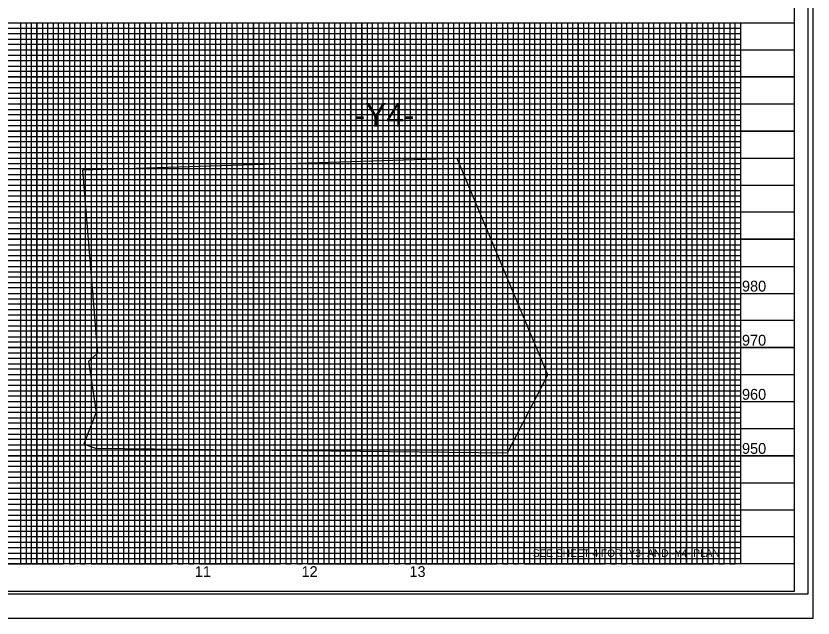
# Model space of a CAD drawing. Extents: x 1624665 to 1626605, y 896887 to 897987.
# Drawn here: x 1625613 to 1626349, y 896887 to 897444 of the extents above; entities that cross this region are included whole.
import ezdxf

# ---------------------------------------------------------------- set-up
doc = ezdxf.new("R2010")
doc.units = 0
for name, color, linetype in [('Prop DSN Text', 7, 'Continuous'), ('Prop PHM Black Shape', 7, 'Continuous'), ('Scratch_Level_1', 7, 'Continuous'), ('Sheet Cutting Line CELL', 7, 'Continuous'), ('Sheet DOT Grid CELL', 7, 'Continuous'), ('Sheet Layout Profile Border Port 2', 7, 'Continuous'), ('Sheet Plot Border Inside CELL', 7, 'Continuous'), ('Sheet Plot Border Outside CELL', 7, 'Continuous'), ('Sheet Profile CELL', 7, 'Continuous'), ('Sheet Profile Grid Major CELL', 7, 'Continuous'), ('Sheet Profile Grid Middle CELL', 7, 'Continuous'), ('Sheet Profile Grid Minor CELL', 7, 'Continuous')]:
    doc.layers.add(name, color=color, linetype=linetype)

msp = doc.modelspace()

# ---------------------------------------------------------------- linework, layer by layer
at = {"layer": 'Prop DSN Text'}
msp.add_lwpolyline([(1625922.4, 897367.44), (1625992.4, 897367.44), (1625992.4, 897337.44), (1625922.4, 897337.44)], close=True, dxfattribs=at)
at = {"layer": 'Prop PHM Black Shape'}
for points in [[(1625922.4, 897367.44), (1625992.4, 897367.44), (1625992.4, 897337.44), (1625922.4, 897337.44)], [(1626082.4, 896957.44), (1626282.4, 896957.44), (1626282.4, 896937.44), (1626082.4, 896937.44)]]:
    msp.add_lwpolyline(points, close=True, dxfattribs=at)
at = {"layer": 'Scratch_Level_1'}
msp.add_lwpolyline([(1625687.54, 897143.34), (1625688.21, 897132.26), (1625680.13, 897124.65), (1625687.11, 897077.78), (1625675.77, 897048.03), (1625686.55, 897044.37), (1626067.2, 897040.06), (1626104.5, 897112.25), (1626020.67, 897312.19), (1625674.55, 897301.26)], close=True, dxfattribs=at)
at = {"layer": 'Sheet Cutting Line CELL'}
msp.add_line((1624665.4, 896887.44), (1626349.4, 896887.44), dxfattribs=at)
at = {"layer": 'Sheet DOT Grid CELL'}
for p, q in [((1624832.4, 897437.44), (1626332.29, 897437.44)), ((1625632.4, 897437.44), (1625632.4, 896937.44)), ((1625682.4, 897437.44), (1625682.4, 896937.44)), ((1625732.4, 897437.44), (1625732.4, 896937.44)), ((1625782.4, 897437.44), (1625782.4, 896937.44)), ((1625832.4, 897437.44), (1625832.4, 896937.44)), ((1625882.4, 897437.44), (1625882.4, 896937.44)), ((1625932.4, 897437.44), (1625932.4, 896937.44)), ((1625982.4, 897437.44), (1625982.4, 896937.44)), ((1626032.4, 897437.44), (1626032.4, 896937.44)), ((1626082.4, 897437.44), (1626082.4, 896937.44)), ((1626132.4, 897437.44), (1626132.4, 896937.44)), ((1626182.4, 897437.44), (1626182.4, 896937.44)), ((1626232.4, 897437.44), (1626232.4, 896937.44)), ((1626282.4, 897437.44), (1626282.4, 896937.44)), ((1624832.4, 897387.44), (1626332.29, 897387.44)), ((1624832.4, 897337.44), (1626332.29, 897337.44)), ((1624832.4, 897287.44), (1626332.29, 897287.44)), ((1624832.4, 897237.44), (1626332.29, 897237.44)), ((1624832.4, 897187.44), (1626332.29, 897187.44)), ((1624832.4, 897137.44), (1626332.29, 897137.44)), ((1624832.4, 897087.44), (1626332.29, 897087.44)), ((1624832.4, 897037.44), (1626332.29, 897037.44)), ((1624832.4, 896987.44), (1626332.29, 896987.44))]:
    msp.add_line(p, q, dxfattribs=at)
at = {"layer": 'Sheet Layout Profile Border Port 2'}
msp.add_lwpolyline([(1624882.4, 897437.44), (1626282.4, 897437.44), (1626282.4, 896937.44), (1624882.4, 896937.44)], close=True, dxfattribs=at)
at = {"layer": 'Sheet Plot Border Inside CELL'}
msp.add_lwpolyline([(1624678.4, 896909.89), (1626344.9, 896909.89), (1626344.9, 897964.99), (1624678.4, 897964.99)], close=True, dxfattribs=at)
at = {"layer": 'Sheet Plot Border Outside CELL'}
msp.add_lwpolyline([(1624665.4, 896887.44), (1626349.4, 896887.44), (1626349.4, 897987.44), (1624665.4, 897987.44)], close=True, dxfattribs=at)
at = {"layer": 'Sheet Profile CELL'}
for p, q in [((1624832.4, 897437.44), (1626332.4, 897437.44)), ((1626332.4, 896937.44), (1624832.4, 896937.44)), ((1624832.4, 896912.44), (1626332.4, 896912.44))]:
    msp.add_line(p, q, dxfattribs=at)
msp.add_lwpolyline([(1626332.4, 897962.44), (1624832.4, 897962.44), (1624832.4, 896912.44), (1626332.4, 896912.44)], close=True, dxfattribs=at)
at = {"layer": 'Sheet Profile Grid Major CELL'}
for p, q in [((1625632.4, 897437.44), (1625682.4, 897437.44)), ((1625732.4, 897437.44), (1625782.4, 897437.44)), ((1625832.4, 897437.44), (1625882.4, 897437.44)), ((1625932.4, 897437.44), (1625982.4, 897437.44)), ((1626032.4, 897437.44), (1626082.4, 897437.44)), ((1626132.4, 897437.44), (1626182.4, 897437.44)), ((1626232.4, 897437.44), (1626282.4, 897437.44)), ((1626232.4, 896937.44), (1626232.4, 896937.44))]:
    msp.add_line(p, q, dxfattribs=at)
for points in [[(1625582.4, 896937.44), (1625632.4, 896937.44), (1625632.4, 897437.44), (1625682.4, 897437.44), (1625682.4, 896937.44), (1625732.4, 896937.44), (1625732.4, 897437.44), (1625782.4, 897437.44), (1625782.4, 896937.44), (1625832.4, 896937.44), (1625832.4, 897437.44), (1625882.4, 897437.44), (1625882.4, 896937.44), (1625932.4, 896937.44), (1625932.4, 897437.44), (1625982.4, 897437.44), (1625982.4, 896937.44), (1626032.4, 896937.44), (1626032.4, 897437.44), (1626082.4, 897437.44), (1626082.4, 896937.44), (1626132.4, 896937.44), (1626132.4, 897437.44), (1626182.4, 897437.44), (1626182.4, 896937.44), (1626232.4, 896937.44), (1626232.4, 896937.44), (1626232.4, 897437.44), (1626282.4, 897437.44), (1626282.4, 896937.44)], [(1626332.4, 897387.44), (1624832.4, 897387.44)], [(1626332.4, 897337.44), (1624832.4, 897337.44), (1624832.4, 897287.44), (1626332.4, 897287.44)], [(1626332.4, 897237.44), (1624832.4, 897237.44), (1624832.4, 897187.44), (1626332.4, 897187.44)], [(1626332.4, 897137.44), (1624832.4, 897137.44), (1624832.4, 897087.44), (1626332.4, 897087.44)], [(1626332.4, 897037.44), (1624832.4, 897037.44), (1624832.4, 897037.44), (1624832.4, 896987.44), (1626332.4, 896987.44)], [(1626332.4, 896937.44), (1624832.4, 896937.44)]]:
    msp.add_lwpolyline(points, dxfattribs=at)
at = {"layer": 'Sheet Profile Grid Middle CELL'}
for points in [[(1625607.4, 896937.44), (1625657.4, 896937.44), (1625657.4, 897437.44), (1625707.4, 897437.44), (1625707.4, 896937.44), (1625757.4, 896937.44), (1625757.4, 897437.44), (1625807.4, 897437.44), (1625807.4, 896937.44), (1625857.4, 896937.44), (1625857.4, 897437.44), (1625907.4, 897437.44), (1625907.4, 896937.44), (1625957.4, 896937.44), (1625957.4, 897437.44), (1626007.4, 897437.44), (1626007.4, 896937.44), (1626057.4, 896937.44), (1626057.4, 897437.44), (1626107.4, 897437.44), (1626107.4, 896937.44), (1626157.4, 896937.44), (1626157.4, 897437.44), (1626207.4, 897437.44), (1626207.4, 896937.44), (1626257.4, 896937.44), (1626257.4, 897437.44)], [(1624832.4, 897412.44), (1626332.4, 897412.44)], [(1626332.4, 897362.44), (1624832.4, 897362.44), (1624832.4, 897312.44), (1626332.4, 897312.44)], [(1626332.4, 897262.44), (1624832.4, 897262.44), (1624832.4, 897212.44), (1626332.4, 897212.44)], [(1626332.4, 897162.44), (1624832.4, 897162.44), (1624832.4, 897112.44), (1626332.4, 897112.44)], [(1626332.4, 897062.44), (1624832.4, 897062.44), (1624832.4, 897012.44), (1626332.4, 897012.44)], [(1626332.4, 896962.44), (1624832.4, 896962.44)]]:
    msp.add_lwpolyline(points, dxfattribs=at)
at = {"layer": 'Sheet Profile Grid Minor CELL'}
for p, q in [((1624882.4, 897432.44), (1626282.4, 897432.44)), ((1626282.4, 897427.44), (1624882.4, 897427.44)), ((1624882.4, 897422.44), (1626282.4, 897422.44)), ((1626282.4, 897417.44), (1624882.4, 897417.44)), ((1624882.4, 897407.44), (1626282.4, 897407.44)), ((1626282.4, 897402.44), (1624882.4, 897402.44)), ((1624882.4, 897397.44), (1626282.4, 897397.44)), ((1626282.4, 897392.44), (1624882.4, 897392.44)), ((1624882.4, 897382.44), (1626282.4, 897382.44)), ((1626282.4, 897377.44), (1624882.4, 897377.44)), ((1624882.4, 897372.44), (1626282.4, 897372.44)), ((1626282.4, 897367.44), (1624882.4, 897367.44)), ((1624882.4, 897357.44), (1626282.4, 897357.44)), ((1626282.4, 897352.44), (1624882.4, 897352.44)), ((1624882.4, 897347.44), (1626282.4, 897347.44)), ((1626282.4, 897342.44), (1624882.4, 897342.44)), ((1624882.4, 897332.44), (1626282.4, 897332.44)), ((1626282.4, 897327.44), (1624882.4, 897327.44)), ((1624882.4, 897322.44), (1626282.4, 897322.44)), ((1626282.4, 897317.44), (1624882.4, 897317.44)), ((1624882.4, 897307.44), (1626282.4, 897307.44)), ((1626282.4, 897302.44), (1624882.4, 897302.44)), ((1624882.4, 897297.44), (1626282.4, 897297.44)), ((1626282.4, 897292.44), (1624882.4, 897292.44)), ((1624882.4, 897282.44), (1626282.4, 897282.44)), ((1626282.4, 897277.44), (1624882.4, 897277.44)), ((1624882.4, 897272.44), (1626282.4, 897272.44)), ((1626282.4, 897267.44), (1624882.4, 897267.44)), ((1624882.4, 897257.44), (1626282.4, 897257.44)), ((1626282.4, 897252.44), (1624882.4, 897252.44)), ((1624882.4, 897247.44), (1626282.4, 897247.44)), ((1626282.4, 897242.44), (1624882.4, 897242.59)), ((1624882.4, 897232.44), (1626282.4, 897232.44)), ((1626282.4, 897227.44), (1624882.4, 897227.44)), ((1624882.4, 897222.44), (1626282.4, 897222.44)), ((1626282.4, 897217.44), (1624882.4, 897217.44)), ((1624882.4, 897207.44), (1626282.4, 897207.44)), ((1626282.4, 897202.44), (1624882.4, 897202.44)), ((1624882.4, 897197.44), (1626282.4, 897197.44)), ((1626282.4, 897192.44), (1624882.4, 897192.44)), ((1624882.4, 897182.44), (1626282.4, 897182.44)), ((1626282.4, 897177.44), (1624882.4, 897177.44)), ((1624882.4, 897172.44), (1626282.4, 897172.44)), ((1626282.4, 897167.44), (1624882.4, 897167.44)), ((1624882.4, 897157.44), (1626282.4, 897157.44)), ((1626282.4, 897152.44), (1624882.4, 897152.44)), ((1624882.4, 897147.44), (1626282.4, 897147.44)), ((1626282.4, 897142.44), (1624882.4, 897142.44)), ((1624882.4, 897132.44), (1626282.4, 897132.44)), ((1626282.4, 897127.44), (1624882.4, 897127.44)), ((1624882.4, 897122.44), (1626282.4, 897122.44)), ((1626282.4, 897117.44), (1624882.4, 897117.44)), ((1624882.4, 897107.44), (1626282.4, 897107.44)), ((1626282.4, 897102.44), (1624882.4, 897102.44)), ((1624882.4, 897097.44), (1626282.4, 897097.44)), ((1626282.4, 897092.44), (1624882.4, 897092.44)), ((1624882.4, 897082.44), (1626282.4, 897082.44)), ((1626282.4, 897077.44), (1624882.4, 897077.44)), ((1624882.4, 897072.44), (1626282.4, 897072.44)), ((1626282.4, 897067.44), (1624882.4, 897067.44)), ((1624882.4, 897057.44), (1626282.4, 897057.44)), ((1626282.4, 897052.44), (1624882.4, 897052.44)), ((1624882.4, 897047.44), (1626282.4, 897047.44)), ((1626282.4, 897042.44), (1624882.4, 897042.44)), ((1624882.4, 897032.44), (1626282.4, 897032.44)), ((1626282.4, 897027.44), (1624882.4, 897027.44)), ((1624882.4, 897022.44), (1626282.4, 897022.44)), ((1626282.4, 897017.44), (1624882.4, 897017.44)), ((1624882.4, 897007.44), (1626282.4, 897007.44)), ((1626282.4, 897002.44), (1624882.4, 897002.44)), ((1624882.4, 896997.44), (1626282.4, 896997.44)), ((1626282.4, 896992.44), (1624882.4, 896992.44)), ((1624882.4, 896982.44), (1626282.4, 896982.44)), ((1626282.4, 896977.44), (1624882.4, 896977.44)), ((1624882.4, 896972.44), (1626282.4, 896972.44)), ((1626282.4, 896967.44), (1624882.4, 896967.44)), ((1624882.4, 896957.44), (1626282.4, 896957.44)), ((1626282.4, 896952.44), (1624882.4, 896952.44)), ((1624882.4, 896947.44), (1626282.4, 896947.44)), ((1624882.4, 896942.44), (1626282.4, 896942.44)), ((1626282.4, 896942.44), (1626282.4, 896942.44))]:
    msp.add_line(p, q, dxfattribs=at)
for points in [[(1625612.4, 896937.44), (1625617.4, 896937.44), (1625617.4, 897437.44), (1625622.4, 897437.44), (1625622.4, 896937.44), (1625627.4, 896937.44), (1625627.4, 897437.44), (1625637.4, 897437.44), (1625637.4, 896937.44), (1625642.4, 896937.44), (1625642.4, 897437.44), (1625647.4, 897437.44), (1625647.4, 896937.44), (1625652.4, 896937.44), (1625652.4, 897437.44), (1625662.4, 897437.44), (1625662.4, 896937.44), (1625667.4, 896937.44), (1625667.4, 897437.44), (1625672.4, 897437.44), (1625672.4, 896937.44), (1625677.4, 896937.44), (1625677.4, 897437.44), (1625687.4, 897437.44), (1625687.4, 896937.44), (1625692.1, 896937.99), (1625692.4, 896937.44), (1625692.4, 897437.44), (1625697.4, 897437.44), (1625697.4, 896937.44), (1625702.4, 896937.44), (1625702.4, 897437.44), (1625712.4, 897437.44), (1625712.4, 896937.44), (1625717.4, 896937.44)], [(1625717.4, 896937.44), (1625717.4, 897437.44), (1625722.4, 897437.44), (1625722.4, 896937.44), (1625727.4, 896937.44), (1625727.4, 897437.44), (1625737.4, 897437.44), (1625737.4, 896937.44), (1625742.4, 896937.44), (1625742.4, 897437.44), (1625747.4, 897437.44), (1625747.4, 896937.44), (1625752.4, 896937.44), (1625752.4, 897437.44), (1625762.4, 897437.44), (1625762.4, 896937.44), (1625767.4, 896937.44), (1625767.4, 897437.44), (1625772.4, 897437.44), (1625772.4, 896937.44), (1625777.4, 896937.44), (1625777.4, 897437.44), (1625787.4, 897437.44), (1625787.4, 896937.44), (1625792.4, 896937.44), (1625792.4, 897437.44), (1625797.4, 897437.44), (1625797.4, 896937.44), (1625802.4, 896937.44), (1625802.4, 897437.44), (1625812.4, 897437.44), (1625812.4, 896937.44), (1625817.4, 896937.44), (1625817.4, 897437.44), (1625822.4, 897437.44), (1625822.4, 896937.44), (1625827.4, 896937.44), (1625827.4, 897437.44), (1625837.4, 897437.44), (1625837.4, 896937.44), (1625842.4, 896937.44), (1625842.4, 897437.44), (1625847.4, 897437.44), (1625847.4, 896937.44), (1625852.4, 896937.44), (1625852.4, 897437.44), (1625862.4, 897437.44), (1625862.4, 896937.44), (1625867.4, 896937.44), (1625867.4, 897437.44), (1625872.4, 897437.44), (1625872.4, 896937.44), (1625877.4, 896937.44), (1625877.4, 897437.44), (1625887.4, 897437.44), (1625887.4, 896937.44), (1625892.4, 896937.44), (1625892.4, 897437.44), (1625897.4, 897437.44), (1625897.4, 896937.44), (1625902.4, 896937.44), (1625902.4, 897437.44), (1625912.4, 897437.44), (1625912.4, 896937.44), (1625917.4, 896937.44), (1625917.4, 897437.44), (1625922.4, 897437.44), (1625922.4, 896937.44), (1625927.4, 896937.44), (1625927.4, 897437.44), (1625937.4, 897437.44), (1625937.4, 896937.44), (1625942.4, 896937.44), (1625942.4, 897437.44), (1625947.4, 897437.44), (1625947.4, 896937.44), (1625952.4, 896937.44), (1625952.4, 897437.44), (1625962.4, 897437.44), (1625962.4, 896937.44), (1625967.4, 896937.44), (1625967.4, 897437.44), (1625972.4, 897437.44), (1625972.4, 896937.44), (1625977.4, 896937.44), (1625977.4, 897437.44), (1625987.4, 897437.44), (1625987.4, 896937.44), (1625992.4, 896937.44), (1625992.4, 897437.44), (1625997.4, 897437.44), (1625997.4, 896937.44), (1626002.4, 896937.44), (1626002.4, 897437.44), (1626012.4, 897437.44), (1626012.4, 896937.44), (1626017.4, 896937.44), (1626017.4, 897437.44), (1626022.4, 897437.44), (1626022.4, 896937.44)], [(1626022.4, 896937.44), (1626027.4, 896937.44), (1626027.4, 897437.44), (1626037.4, 897437.44), (1626037.4, 896937.44), (1626042.4, 896937.44), (1626042.4, 897437.44), (1626047.4, 897437.44), (1626047.4, 896937.44), (1626052.4, 896937.44), (1626052.4, 897437.44), (1626062.4, 897437.44), (1626062.4, 896937.44), (1626067.4, 896937.44), (1626067.4, 897437.44), (1626072.4, 897437.44), (1626072.4, 896937.44), (1626077.4, 896937.44), (1626077.4, 897437.44), (1626087.4, 897437.44), (1626087.4, 896937.44), (1626092.4, 896937.44), (1626092.4, 897437.44), (1626097.4, 897437.44), (1626097.4, 896937.44), (1626102.4, 896937.44), (1626102.4, 897437.44), (1626112.4, 897437.44), (1626112.4, 896937.44), (1626117.4, 896937.44), (1626117.4, 897437.44), (1626122.4, 897437.44), (1626122.4, 896937.44), (1626127.4, 896937.44), (1626127.4, 897437.44), (1626137.4, 897437.44), (1626137.4, 896937.44), (1626142.4, 896937.44), (1626142.4, 897437.44), (1626147.4, 897437.44), (1626147.4, 896937.44), (1626152.4, 896937.44), (1626152.4, 897437.44), (1626162.4, 897437.44), (1626162.4, 896937.44), (1626167.4, 896937.44), (1626167.4, 897437.44), (1626172.4, 897437.44), (1626172.4, 896937.44), (1626177.4, 896937.44), (1626177.4, 897437.44), (1626187.4, 897437.44), (1626187.4, 896937.44), (1626192.4, 896937.44), (1626192.4, 897437.44), (1626197.4, 897437.44), (1626197.4, 896937.44), (1626202.4, 896937.44), (1626202.4, 897437.44), (1626212.4, 897437.44), (1626212.4, 896937.44), (1626217.4, 896937.44), (1626217.4, 897437.44), (1626222.4, 897437.44), (1626222.4, 896937.44), (1626227.4, 896937.44), (1626227.4, 897437.44), (1626237.4, 897437.44), (1626237.4, 896937.44), (1626242.4, 896937.44), (1626242.4, 897437.44), (1626247.4, 897437.44), (1626247.4, 896937.44), (1626252.4, 896937.44), (1626252.4, 897437.44), (1626262.4, 897437.44), (1626262.4, 896937.44), (1626267.4, 896937.44), (1626267.4, 897437.44), (1626272.4, 897437.44), (1626272.4, 896937.44), (1626277.4, 896937.44), (1626277.4, 897437.44), (1626282.4, 897437.44)]]:
    msp.add_lwpolyline(points, dxfattribs=at)

# ---------------------------------------------------------------- texts
at = {"layer": 'Prop DSN Text'}
for s, height, p in [('-Y4-', 21.875, (1625925.95, 897341.5)), ('980', 10, (1626283.75, 897189.17)), ('970', 10, (1626283.75, 897139.17)), ('960', 10, (1626283.75, 897089.17)), ('950', 10, (1626283.75, 897039.17)), ('11', 10, (1625778.28, 896925.38)), ('12', 10, (1625876.85, 896925.38)), ('13', 10, (1625976.53, 896925.38))]:
    msp.add_text(s, height=height, dxfattribs=at).set_placement(p)
at = {"layer": 'Prop PHM Black Shape'}
msp.add_text('SEE SHEET 4 FOR -Y3- AND -Y4- PLAN', height=7, dxfattribs=at).set_placement((1626090.53, 896943.94))

doc.saveas('drawing.dxf')
